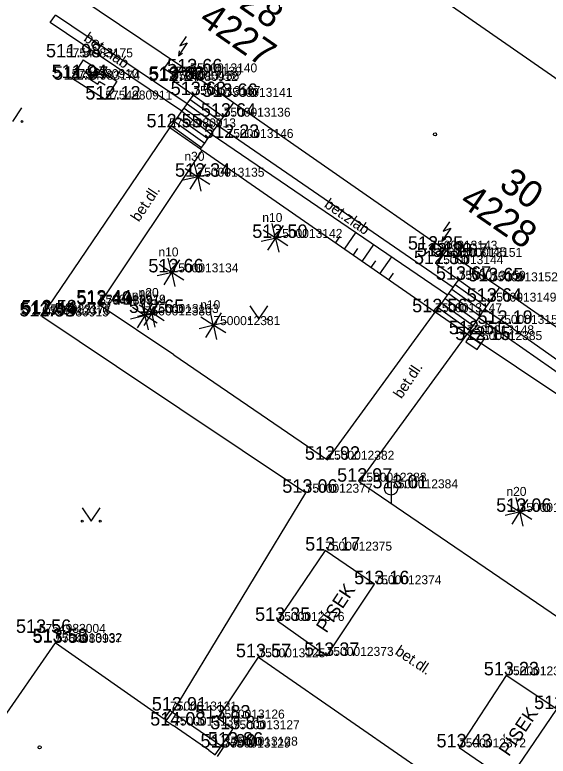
# Model space of a CAD drawing. Extents: x -669251 to -668549, y -1128351 to -1127698.
# Drawn here: x -668998.51 to -668968.88, y -1127892.22 to -1127851.01 of the extents above; entities that cross this region are included whole.
import ezdxf

# ---------------------------------------------------------------- set-up
doc = ezdxf.new("R2010")
doc.units = 0
for name, color, linetype in [('Vrstva 1', 7, 'Continuous'), ('Vrstva 10', 7, 'Continuous'), ('Vrstva 11', 7, 'Continuous'), ('Vrstva 14', 7, 'Continuous'), ('Vrstva 15', 7, 'Continuous'), ('Vrstva 2', 7, 'Continuous'), ('Vrstva 22', 7, 'Continuous'), ('Vrstva 24', 7, 'Continuous'), ('Vrstva 27', 7, 'Continuous'), ('Vrstva 3', 7, 'Continuous'), ('Vrstva 36', 7, 'Continuous'), ('Vrstva 40', 7, 'Continuous'), ('Vrstva 42', 7, 'Continuous'), ('Vrstva 43', 7, 'Continuous'), ('Vrstva 44', 7, 'Continuous'), ('Vrstva 47', 7, 'Continuous'), ('Vrstva 5', 7, 'Continuous'), ('Vrstva 58', 7, 'Continuous'), ('Vrstva 6', 7, 'Continuous')]:
    doc.layers.add(name, color=color, linetype=linetype)

msp = doc.modelspace()

# ---------------------------------------------------------------- linework, layer by layer
at = {"layer": 'Vrstva 1'}
for p, q in [((-668995.671, -1127853.376), (-668995.671, -1127853.376)), ((-668988.767, -1127854.212), (-668988.767, -1127854.212)), ((-668995.356, -1127854.529), (-668995.356, -1127854.529)), ((-668995.274, -1127854.619), (-668995.274, -1127854.619)), ((-668989.766, -1127854.624), (-668989.766, -1127854.624)), ((-668989.624, -1127854.391), (-668989.624, -1127854.391)), ((-668989.843, -1127854.69), (-668989.843, -1127854.69)), ((-668993.486, -1127855.721), (-668993.486, -1127855.721)), ((-668988.589, -1127855.475), (-668988.589, -1127855.475)), ((-668986.808, -1127855.573), (-668986.808, -1127855.573)), ((-668986.912, -1127856.676), (-668986.912, -1127856.676)), ((-668989.948, -1127857.268), (-668989.948, -1127857.268)), ((-668986.749, -1127857.854), (-668986.749, -1127857.854)), ((-668988.363, -1127860.013), (-668988.363, -1127860.013)), ((-668984.034, -1127863.413), (-668984.034, -1127863.413)), ((-668975.422, -1127864.067), (-668975.422, -1127864.067)), ((-668974.92, -1127864.442), (-668974.92, -1127864.442)), ((-668974.042, -1127864.467), (-668974.042, -1127864.467)), ((-668975.087, -1127864.871), (-668975.087, -1127864.871)), ((-668989.807, -1127865.33), (-668989.807, -1127865.33)), ((-668973.853, -1127865.742), (-668973.853, -1127865.742)), ((-668972.062, -1127865.829), (-668972.062, -1127865.829)), ((-668972.142, -1127866.959), (-668972.142, -1127866.959)), ((-668993.848, -1127867.067), (-668993.848, -1127867.067)), ((-668993.822, -1127867.125), (-668993.822, -1127867.125)), ((-668997.007, -1127867.779), (-668997.007, -1127867.779)), ((-668996.935, -1127867.687), (-668996.935, -1127867.687)), ((-668996.892, -1127867.613), (-668996.892, -1127867.613)), ((-668991.29, -1127867.725), (-668991.29, -1127867.725)), ((-668990.907, -1127867.586), (-668990.907, -1127867.586)), ((-668975.164, -1127867.546), (-668975.164, -1127867.546)), ((-668971.696, -1127868.191), (-668971.696, -1127868.191)), ((-668987.484, -1127868.262), (-668987.484, -1127868.262)), ((-668973.385, -1127868.773), (-668973.385, -1127868.773)), ((-668972.931, -1127869.093), (-668972.931, -1127869.093)), ((-668981.148, -1127875.747), (-668981.148, -1127875.747)), ((-668979.355, -1127876.966), (-668979.355, -1127876.966)), ((-668982.357, -1127877.581), (-668982.357, -1127877.581)), ((-668977.609, -1127877.335), (-668977.609, -1127877.335)), ((-668970.473, -1127878.642), (-668970.473, -1127878.642)), ((-668981.272, -1127880.798), (-668981.272, -1127880.798)), ((-668978.528, -1127882.666), (-668978.528, -1127882.666)), ((-668983.915, -1127884.705), (-668983.915, -1127884.705)), ((-668997.177, -1127885.372), (-668997.177, -1127885.372)), ((-668996.279, -1127885.886), (-668996.279, -1127885.886)), ((-668996.268, -1127885.924), (-668996.268, -1127885.924)), ((-668984.978, -1127886.729), (-668984.978, -1127886.729)), ((-668981.187, -1127886.651), (-668981.187, -1127886.651)), ((-668971.207, -1127887.732), (-668971.207, -1127887.732)), ((-668989.886, -1127889.689), (-668989.886, -1127889.689)), ((-668987.237, -1127890.134), (-668987.237, -1127890.134)), ((-668989.718, -1127890.523), (-668989.718, -1127890.523)), ((-668986.403, -1127890.728), (-668986.403, -1127890.728)), ((-668986.511, -1127891.64), (-668986.511, -1127891.64)), ((-668986.912, -1127891.744), (-668986.912, -1127891.744)), ((-668973.834, -1127891.738), (-668973.834, -1127891.738))]:
    msp.add_line(p, q, dxfattribs=at)
at = {"layer": 'Vrstva 10'}
for p, q in [((-668996.542, -1127851.438), (-668996.262, -1127851.024)), ((-668988.94, -1127855.965), (-668996.262, -1127851.024)), ((-668989.231, -1127856.372), (-668996.542, -1127851.438)), ((-668997.007, -1127867.779), (-668989.898, -1127857.303)), ((-668974.163, -1127866.169), (-668987.261, -1127857.164)), ((-668974.474, -1127866.598), (-668987.611, -1127857.652)), ((-668993.822, -1127867.125), (-668988.106, -1127858.548)), ((-668988.204, -1127858.48), (-668988.106, -1127858.548)), ((-668989.671, -1127869.913), (-668993.822, -1127867.125)), ((-668971.543, -1127867.968), (-668972.421, -1127867.366)), ((-668992.856, -1127870.567), (-668997.007, -1127867.779)), ((-668981.148, -1127875.747), (-668975.164, -1127867.546)), ((-668971.875, -1127868.452), (-668972.753, -1127867.85)), ((-668959.447, -1127876.548), (-668971.543, -1127867.968)), ((-668959.721, -1127876.99), (-668971.875, -1127868.452)), ((-668979.355, -1127876.966), (-668973.385, -1127868.773)), ((-668989.671, -1127869.913), (-668981.148, -1127875.747)), ((-668982.357, -1127877.581), (-668992.856, -1127870.567)), ((-668979.355, -1127876.966), (-668966.01, -1127886.091)), ((-668982.357, -1127877.581), (-668989.763, -1127889.775)), ((-668981.272, -1127880.798), (-668983.915, -1127884.705)), ((-668978.528, -1127882.666), (-668981.272, -1127880.798)), ((-668981.187, -1127886.651), (-668978.528, -1127882.666)), ((-668983.915, -1127884.705), (-668981.187, -1127886.651)), ((-668987.237, -1127890.134), (-668984.978, -1127886.729)), ((-668984.978, -1127886.729), (-668972.065, -1127895.659)), ((-668971.207, -1127887.732), (-668973.834, -1127891.738)), ((-668968.407, -1127889.606), (-668971.207, -1127887.732)), ((-668971.113, -1127893.598), (-668968.407, -1127889.606)), ((-668986.403, -1127890.728), (-668987.237, -1127890.134)), ((-668987.035, -1127891.658), (-668986.403, -1127890.728)), ((-668973.834, -1127891.738), (-668971.113, -1127893.598))]:
    msp.add_line(p, q, dxfattribs=at)
at = {"layer": 'Vrstva 11'}
for p, q in [((-668989.262, -1127853.878), (-668989.766, -1127854.624)), ((-668989.766, -1127854.624), (-668988.589, -1127855.475)), ((-668988.94, -1127855.965), (-668988.764, -1127855.719)), ((-668988.764, -1127855.719), (-668988.589, -1127855.475)), ((-668988.764, -1127855.719), (-668987.087, -1127856.92)), ((-668988.589, -1127855.475), (-668986.912, -1127856.676)), ((-668989.231, -1127856.372), (-668989.113, -1127856.207)), ((-668989.113, -1127856.207), (-668988.94, -1127855.965)), ((-668989.113, -1127856.207), (-668987.436, -1127857.408)), ((-668988.94, -1127855.965), (-668987.261, -1127857.164)), ((-668986.361, -1127855.885), (-668986.912, -1127856.676)), ((-668989.637, -1127856.938), (-668989.462, -1127856.695)), ((-668989.462, -1127856.695), (-668989.231, -1127856.372)), ((-668989.462, -1127856.695), (-668987.785, -1127857.896)), ((-668989.231, -1127856.372), (-668987.611, -1127857.652)), ((-668987.087, -1127856.92), (-668986.912, -1127856.676)), ((-668989.812, -1127857.182), (-668989.637, -1127856.938)), ((-668989.637, -1127856.938), (-668987.96, -1127858.14)), ((-668987.261, -1127857.164), (-668987.087, -1127856.92)), ((-668989.898, -1127857.303), (-668989.812, -1127857.182)), ((-668988.204, -1127858.48), (-668989.898, -1127857.303)), ((-668989.812, -1127857.182), (-668988.135, -1127858.383)), ((-668987.611, -1127857.652), (-668987.436, -1127857.408)), ((-668987.436, -1127857.408), (-668987.261, -1127857.164)), ((-668987.96, -1127858.14), (-668987.785, -1127857.896)), ((-668987.785, -1127857.896), (-668987.611, -1127857.652)), ((-668988.135, -1127858.383), (-668987.96, -1127858.14)), ((-668988.204, -1127858.48), (-668988.135, -1127858.383)), ((-668974.556, -1127864.109), (-668975.087, -1127864.871)), ((-668975.087, -1127864.871), (-668973.853, -1127865.742)), ((-668974.041, -1127866.001), (-668973.853, -1127865.742)), ((-668973.853, -1127865.742), (-668972.142, -1127866.959)), ((-668974.229, -1127866.26), (-668974.163, -1127866.169)), ((-668974.163, -1127866.169), (-668974.041, -1127866.001)), ((-668974.041, -1127866.001), (-668972.323, -1127867.223)), ((-668971.586, -1127866.161), (-668972.142, -1127866.959)), ((-668974.407, -1127866.506), (-668972.685, -1127867.751)), ((-668974.229, -1127866.26), (-668972.504, -1127867.487)), ((-668974.794, -1127867.036), (-668974.606, -1127866.778)), ((-668974.606, -1127866.778), (-668972.866, -1127868.015)), ((-668972.142, -1127866.959), (-668972.323, -1127867.223)), ((-668975.164, -1127867.546), (-668974.982, -1127867.295)), ((-668974.982, -1127867.295), (-668974.794, -1127867.036)), ((-668974.982, -1127867.295), (-668973.227, -1127868.543)), ((-668974.794, -1127867.036), (-668973.047, -1127868.279)), ((-668972.421, -1127867.366), (-668972.504, -1127867.487)), ((-668972.323, -1127867.223), (-668972.421, -1127867.366)), ((-668973.385, -1127868.773), (-668975.164, -1127867.546)), ((-668972.685, -1127867.751), (-668972.753, -1127867.85)), ((-668972.504, -1127867.487), (-668972.685, -1127867.751)), ((-668972.866, -1127868.015), (-668973.047, -1127868.279)), ((-668972.753, -1127867.85), (-668972.866, -1127868.015)), ((-668973.227, -1127868.543), (-668973.385, -1127868.773)), ((-668973.047, -1127868.279), (-668973.227, -1127868.543))]:
    msp.add_line(p, q, dxfattribs=at)
msp.add_lwpolyline([(-668974.606, -1127866.778), (-668974.474, -1127866.598), (-668974.407, -1127866.506), (-668974.229, -1127866.26)], dxfattribs=at)
at = {"layer": 'Vrstva 14'}
for p, q in [((-668975.164, -1127867.546), (-668988.106, -1127858.548)), ((-668960.117, -1127877.629), (-668973.385, -1127868.773))]:
    msp.add_line(p, q, dxfattribs=at)
at = {"layer": 'Vrstva 15'}
for p, q in [((-668980.206, -1127864.041), (-668979.552, -1127863.1)), ((-668980.699, -1127863.698), (-668980.438, -1127863.323)), ((-668979.713, -1127864.383), (-668979.451, -1127864.005)), ((-668979.221, -1127864.725), (-668978.563, -1127863.779)), ((-668978.236, -1127865.411), (-668977.573, -1127864.458)), ((-668978.728, -1127865.068), (-668978.464, -1127864.688)), ((-668977.743, -1127865.753), (-668977.477, -1127865.371))]:
    msp.add_line(p, q, dxfattribs=at)
at = {"layer": 'Vrstva 22'}
for p, q in [((-668988.397, -1127859.993), (-668989.053, -1127859.579)), ((-668988.371, -1127859.973), (-668988.543, -1127859.219)), ((-668987.929, -1127859.323), (-668988.343, -1127859.979)), ((-668988.323, -1127860.005), (-668987.569, -1127859.833)), ((-668989.157, -1127860.193), (-668988.403, -1127860.021)), ((-668988.383, -1127860.047), (-668988.797, -1127860.703)), ((-668988.355, -1127860.053), (-668988.183, -1127860.807)), ((-668987.673, -1127860.447), (-668988.329, -1127860.033)), ((-668984.042, -1127863.373), (-668984.214, -1127862.619)), ((-668983.6, -1127862.723), (-668984.014, -1127863.379)), ((-668984.068, -1127863.393), (-668984.724, -1127862.979)), ((-668983.994, -1127863.405), (-668983.24, -1127863.233)), ((-668984.828, -1127863.593), (-668984.074, -1127863.421)), ((-668984.054, -1127863.447), (-668984.468, -1127864.103)), ((-668984.026, -1127863.453), (-668983.854, -1127864.207)), ((-668983.344, -1127863.847), (-668984, -1127863.433)), ((-668989.841, -1127865.31), (-668990.497, -1127864.896)), ((-668989.815, -1127865.29), (-668989.987, -1127864.536)), ((-668989.373, -1127864.64), (-668989.787, -1127865.296)), ((-668990.601, -1127865.51), (-668989.847, -1127865.338)), ((-668989.117, -1127865.764), (-668989.773, -1127865.35)), ((-668989.767, -1127865.322), (-668989.013, -1127865.15)), ((-668989.827, -1127865.364), (-668990.241, -1127866.02)), ((-668989.799, -1127865.37), (-668989.627, -1127866.124)), ((-668991.298, -1127867.685), (-668991.47, -1127866.931)), ((-668990.915, -1127867.546), (-668991.087, -1127866.792)), ((-668990.473, -1127866.896), (-668990.887, -1127867.552)), ((-668991.324, -1127867.705), (-668991.98, -1127867.291)), ((-668990.941, -1127867.566), (-668991.597, -1127867.152)), ((-668990.856, -1127867.035), (-668991.27, -1127867.691)), ((-668990.867, -1127867.578), (-668990.113, -1127867.406)), ((-668992.084, -1127867.905), (-668991.33, -1127867.733)), ((-668991.31, -1127867.759), (-668991.724, -1127868.415)), ((-668991.701, -1127867.766), (-668990.947, -1127867.594)), ((-668990.927, -1127867.62), (-668991.341, -1127868.276)), ((-668991.282, -1127867.765), (-668991.11, -1127868.519)), ((-668990.6, -1127868.159), (-668991.256, -1127867.745)), ((-668991.25, -1127867.717), (-668990.496, -1127867.545)), ((-668990.899, -1127867.626), (-668990.727, -1127868.38)), ((-668990.217, -1127868.02), (-668990.873, -1127867.606)), ((-668987.518, -1127868.242), (-668988.174, -1127867.828)), ((-668987.492, -1127868.222), (-668987.664, -1127867.468)), ((-668987.05, -1127867.572), (-668987.464, -1127868.228)), ((-668987.444, -1127868.254), (-668986.69, -1127868.082)), ((-668988.278, -1127868.442), (-668987.524, -1127868.27)), ((-668987.504, -1127868.296), (-668987.918, -1127868.952)), ((-668987.476, -1127868.302), (-668987.304, -1127869.056)), ((-668986.794, -1127868.696), (-668987.45, -1127868.282)), ((-668970.481, -1127878.602), (-668970.653, -1127877.848)), ((-668970.039, -1127877.952), (-668970.453, -1127878.608)), ((-668970.507, -1127878.622), (-668971.163, -1127878.208)), ((-668970.433, -1127878.634), (-668969.679, -1127878.462)), ((-668971.267, -1127878.822), (-668970.513, -1127878.65)), ((-668970.493, -1127878.676), (-668970.907, -1127879.332)), ((-668970.465, -1127878.682), (-668970.293, -1127879.436)), ((-668969.783, -1127879.076), (-668970.439, -1127878.662))]:
    msp.add_line(p, q, dxfattribs=at)
for centre in [(-668988.363, -1127860.013), (-668984.034, -1127863.413), (-668989.807, -1127865.33), (-668991.29, -1127867.725), (-668990.907, -1127867.586), (-668987.484, -1127868.262), (-668970.473, -1127878.642)]:
    msp.add_circle(centre, 0.04, dxfattribs=at)
at = {"layer": 'Vrstva 24'}
for p, q in [((-668988.933, -1127852.562), (-668989.423, -1127853.287)), ((-668989, -1127852.214), (-668989.35, -1127852.733)), ((-668989.35, -1127852.733), (-668988.933, -1127852.562)), ((-668989.377, -1127853.022), (-668989.423, -1127853.287)), ((-668989.423, -1127853.287), (-668989.195, -1127853.145)), ((-668994.711, -1127853.517), (-668995.356, -1127854.529)), ((-668994.711, -1127853.517), (-668992.841, -1127854.709)), ((-668990.212, -1127853.994), (-668989.854, -1127853.479)), ((-668990.212, -1127853.994), (-668989.614, -1127854.398)), ((-668993.486, -1127855.721), (-668995.356, -1127854.529)), ((-668992.841, -1127854.709), (-668993.486, -1127855.721)), ((-668974.297, -1127862.868), (-668974.787, -1127863.593)), ((-668974.364, -1127862.52), (-668974.714, -1127863.039)), ((-668974.714, -1127863.039), (-668974.297, -1127862.868)), ((-668975.159, -1127863.689), (-668975.422, -1127864.067)), ((-668974.741, -1127863.328), (-668974.787, -1127863.593)), ((-668974.787, -1127863.593), (-668974.559, -1127863.451)), ((-668974.92, -1127864.442), (-668975.422, -1127864.067)), ((-668974.645, -1127864.047), (-668974.92, -1127864.442))]:
    msp.add_line(p, q, dxfattribs=at)
msp.add_lwpolyline([(-668994.581, -1127854.214), (-668994.271, -1127854.413), (-668994.37, -1127854.567), (-668993.904, -1127854.864), (-668993.805, -1127854.71), (-668993.494, -1127854.907)], dxfattribs=at)
at = {"layer": 'Vrstva 27'}
for p, q in [((-668973.239, -1127868.88), (-668972.622, -1127869.306)), ((-668977.609, -1127876.96), (-668977.609, -1127878.21))]:
    msp.add_line(p, q, dxfattribs=at)
msp.add_lwpolyline([(-668973.452, -1127869.188), (-668972.834, -1127869.614), (-668972.408, -1127868.996), (-668973.026, -1127868.57)], close=True, dxfattribs=at)
msp.add_circle((-668977.609, -1127877.335), 0.375, dxfattribs=at)
at = {"layer": 'Vrstva 36'}
for p, q in [((-668998.616, -1127856.939), (-668998.116, -1127856.189)), ((-668985.465, -1127867.19), (-668984.965, -1127867.94)), ((-668984.965, -1127867.94), (-668984.465, -1127867.19)), ((-668994.766, -1127878.414), (-668994.266, -1127879.164)), ((-668994.266, -1127879.164), (-668993.766, -1127878.414))]:
    msp.add_line(p, q, dxfattribs=at)
for centre in [(-668998.115, -1127856.939), (-668985.465, -1127867.94), (-668984.465, -1127867.94), (-668994.766, -1127879.164), (-668993.766, -1127879.164)]:
    msp.add_circle(centre, 0.05, dxfattribs=at)
at = {"layer": 'Vrstva 5'}
for p, q in [((-668979.837, -1127846.614), (-668968.035, -1127854.821)), ((-668989.262, -1127853.878), (-668995.395, -1127849.739)), ((-668988.767, -1127854.212), (-668989.262, -1127853.878)), ((-668986.808, -1127855.573), (-668986.361, -1127855.885)), ((-668986.361, -1127855.885), (-668974.556, -1127864.109)), ((-668974.556, -1127864.109), (-668974.042, -1127864.467)), ((-668972.062, -1127865.829), (-668971.586, -1127866.161)), ((-668971.586, -1127866.161), (-668959.752, -1127874.401)), ((-668996.268, -1127885.924), (-669002.798, -1127895.331)), ((-668990.223, -1127890.169), (-668996.268, -1127885.924)), ((-668990.223, -1127890.169), (-668989.886, -1127889.689)), ((-668990.1, -1127890.255), (-668989.763, -1127889.775)), ((-668989.886, -1127889.689), (-668989.763, -1127889.775)), ((-668989.763, -1127889.775), (-668987.035, -1127891.658)), ((-668990.1, -1127890.255), (-668989.717, -1127890.524)), ((-668987.376, -1127892.149), (-668987.035, -1127891.658)), ((-668987.035, -1127891.658), (-668986.912, -1127891.744)), ((-668987.738, -1127891.898), (-668987.376, -1127892.149)), ((-668987.253, -1127892.235), (-668986.912, -1127891.744))]:
    msp.add_line(p, q, dxfattribs=at)
at = {"layer": 'Vrstva 58'}
for centre in [(-668975.169, -1127857.656), (-668997.135, -1127891.734)]:
    msp.add_circle(centre, 0.0875, dxfattribs=at)
at = {"layer": 'Vrstva 6'}
for p, q in [((-668988.767, -1127854.212), (-668986.808, -1127855.573)), ((-668974.042, -1127864.467), (-668972.062, -1127865.829)), ((-668987.738, -1127891.898), (-668989.717, -1127890.524))]:
    msp.add_line(p, q, dxfattribs=at)

# ---------------------------------------------------------------- texts
at = {"layer": 'Vrstva 2'}
for s, p in [('5754983175', (-668995.671, -1127853.376)), ('7500013140', (-668988.767, -1127854.212)), ('5754980910', (-668995.356, -1127854.529)), ('5754983174', (-668995.274, -1127854.619)), ('5754980912', (-668989.843, -1127854.69)), ('7500013138', (-668989.766, -1127854.624)), ('7500013139', (-668989.624, -1127854.391)), ('7500013137', (-668988.589, -1127855.475)), ('5754980911', (-668993.486, -1127855.721)), ('7500013141', (-668986.808, -1127855.573)), ('7500013136', (-668986.912, -1127856.676)), ('5754980913', (-668989.948, -1127857.268)), ('7500013146', (-668986.749, -1127857.854)), ('7500013135', (-668988.363, -1127860.013)), ('7500013142', (-668984.034, -1127863.413)), ('7500013143', (-668975.422, -1127864.067)), ('7500013145', (-668974.92, -1127864.442)), ('7500013151', (-668974.042, -1127864.467)), ('7500013144', (-668975.087, -1127864.871)), ('7500013134', (-668989.807, -1127865.33)), ('7500013150', (-668973.853, -1127865.742)), ('7500013152', (-668972.062, -1127865.829)), ('7500012379', (-668993.848, -1127867.067)), ('7500013149', (-668972.142, -1127866.959)), ('5754980914', (-668993.822, -1127867.125)), ('5754980915', (-668997.007, -1127867.779)), ('7500012378', (-668996.935, -1127867.687)), ('5754983177', (-668996.892, -1127867.613)), ('7500012380', (-668991.29, -1127867.725)), ('7500013133', (-668990.907, -1127867.586)), ('7500013147', (-668975.164, -1127867.546)), ('7500012381', (-668987.484, -1127868.262)), ('7500013153', (-668971.696, -1127868.191)), ('7500013148', (-668973.385, -1127868.773)), ('7500012385', (-668972.931, -1127869.093)), ('7500012382', (-668981.148, -1127875.747)), ('7500012383', (-668979.355, -1127876.966)), ('7500012384', (-668977.609, -1127877.335)), ('7500012377', (-668982.357, -1127877.581)), ('7500013154', (-668970.473, -1127878.642)), ('7500012375', (-668981.272, -1127880.798)), ('7500012374', (-668978.528, -1127882.666)), ('7500012376', (-668983.915, -1127884.705)), ('5754983004', (-668997.177, -1127885.372)), ('7500013132', (-668996.279, -1127885.886)), ('5754980937', (-668996.268, -1127885.924)), ('7500013125', (-668984.978, -1127886.729)), ('7500012373', (-668981.187, -1127886.651)), ('7500012371', (-668971.207, -1127887.732)), ('7500013131', (-668989.886, -1127889.689)), ('7500013126', (-668987.237, -1127890.134)), ('7500013130', (-668989.718, -1127890.523)), ('7500013127', (-668986.403, -1127890.728)), ('7500013129', (-668986.912, -1127891.744)), ('7500013128', (-668986.511, -1127891.64)), ('7500012372', (-668973.834, -1127891.738))]:
    msp.add_text(s, height=0.5, dxfattribs=at).set_placement(p)
at = {"layer": 'Vrstva 3'}
for s, p in [('511.98 ', (-668996.783, -1127853.376)), ('511.94 ', (-668996.468, -1127854.529)), ('513.66 ', (-668990.055, -1127854.212)), ('511.97 ', (-668996.386, -1127854.619)), ('512.27 ', (-668991.095, -1127854.69)), ('513.66 ', (-668991.054, -1127854.624)), ('512.12 ', (-668994.596, -1127855.721)), ('513.63 ', (-668989.855, -1127855.475)), ('513.66 ', (-668988.096, -1127855.573)), ('513.64 ', (-668988.178, -1127856.676)), ('512.55 ', (-668991.2, -1127857.268)), ('512.23 ', (-668988.001, -1127857.854)), ('512.34 ', (-668989.615, -1127860.013)), ('512.50 ', (-668985.322, -1127863.413)), ('512.35 ', (-668976.674, -1127864.067)), ('512.39 ', (-668976.175, -1127864.442)), ('513.67 ', (-668975.308, -1127864.467)), ('512.35 ', (-668976.339, -1127864.871)), ('512.66 ', (-668991.095, -1127865.33)), ('513.67 ', (-668975.119, -1127865.742)), ('513.65 ', (-668973.328, -1127865.829)), ('512.44 ', (-668995.1, -1127867.067)), ('512.49 ', (-668995.077, -1127867.125)), ('513.64 ', (-668973.408, -1127866.959)), ('512.44 ', (-668998.187, -1127867.687)), ('512.58 ', (-668998.144, -1127867.613)), ('512.65 ', (-668992.173, -1127867.586)), ('512.56 ', (-668976.438, -1127867.546)), ('512.53 ', (-668998.259, -1127867.779)), ('512.19 ', (-668972.81, -1127868.191)), ('512.51 ', (-668974.4, -1127868.773)), ('512.15 ', (-668974.041, -1127869.093)), ('512.92 ', (-668982.402, -1127875.747)), ('512.97 ', (-668980.609, -1127876.966)), ('513.06 ', (-668983.653, -1127877.581)), ('513.01 ', (-668978.646, -1127877.335)), ('513.06 ', (-668971.769, -1127878.642)), ('513.17 ', (-668982.382, -1127880.798)), ('513.16 ', (-668979.661, -1127882.666)), ('513.35 ', (-668985.167, -1127884.705)), ('513.56 ', (-668998.451, -1127885.372)), ('513.53 ', (-668997.531, -1127885.886)), ('513.55 ', (-668997.52, -1127885.924)), ('513.37 ', (-668982.439, -1127886.651)), ('513.57 ', (-668986.23, -1127886.729)), ('513.23 ', (-668972.459, -1127887.732)), ('513.29 ', (-668969.662, -1127889.606)), ('513.91 ', (-668990.903, -1127889.689)), ('513.83 ', (-668988.489, -1127890.134)), ('514.03 ', (-668990.992, -1127890.523)), ('513.85 ', (-668987.655, -1127890.728)), ('513.86 ', (-668987.785, -1127891.64)), ('513.90 ', (-668988.202, -1127891.744)), ('513.43 ', (-668975.086, -1127891.738))]:
    msp.add_text(s, height=0.75, dxfattribs=at).set_placement(p)
at = {"layer": 'Vrstva 40'}
for s, rotation, p in [('bet.zlab', 325.1908, (-668994.731, -1127852.425)), ('bet.dl.', 56.3192, (-668991.622, -1127862.562)), ('bet.zlab', 325.1908, (-668981.369, -1127861.665)), ('bet.dl.', 56.3192, (-668977.034, -1127872.397)), ('bet.dl.', 326.3192, (-668977.434, -1127886.524))]:
    msp.add_text(s, height=0.6, rotation=rotation, dxfattribs=at).set_placement(p)
at = {"layer": 'Vrstva 42'}
for rotation, p in [(56.2867, (-668981.208, -1127885.422)), (55.8684, (-668971.067, -1127892.283))]:
    msp.add_text('PÍSEK', height=0.75, rotation=rotation, dxfattribs=at).set_placement(p)
at = {"layer": 'Vrstva 43'}
for s, rotation, p in [('4227', 325.2107, (-668988.361, -1127851.45)), ('4228', 325.4767, (-668973.869, -1127861.552))]:
    msp.add_text(s, height=1.5, rotation=rotation, dxfattribs=at).set_placement(p)
at = {"layer": 'Vrstva 44'}
for s, rotation, p in [('28', 325.2107, (-668986.115, -1127850.576)), ('30', 325.4767, (-668971.681, -1127860.629))]:
    msp.add_text(s, height=1.5, rotation=rotation, dxfattribs=at).set_placement(p)
at = {"layer": 'Vrstva 47'}
for s, p in [('n30', (-668989.093, -1127859.127)), ('n10', (-668984.764, -1127862.527)), ('n10', (-668990.537, -1127864.444)), ('n10', (-668992.02, -1127866.839)), ('n20', (-668991.637, -1127866.7)), ('n10', (-668988.214, -1127867.376)), ('n20', (-668971.203, -1127877.756))]:
    msp.add_text(s, height=0.5, dxfattribs=at).set_placement(p)

doc.saveas('drawing.dxf')
